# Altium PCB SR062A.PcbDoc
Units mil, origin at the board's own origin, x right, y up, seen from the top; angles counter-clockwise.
Board outline 3000 x 3000 mil, 4 copper layers (Top Layer, Signal Layer 1, Signal Layer 2, Bottom Layer), stack 40.024 mil thick; 38 components, 10 nets, 80 pads, 245 vias.
Unrouted connection lines stored in the file: 3.
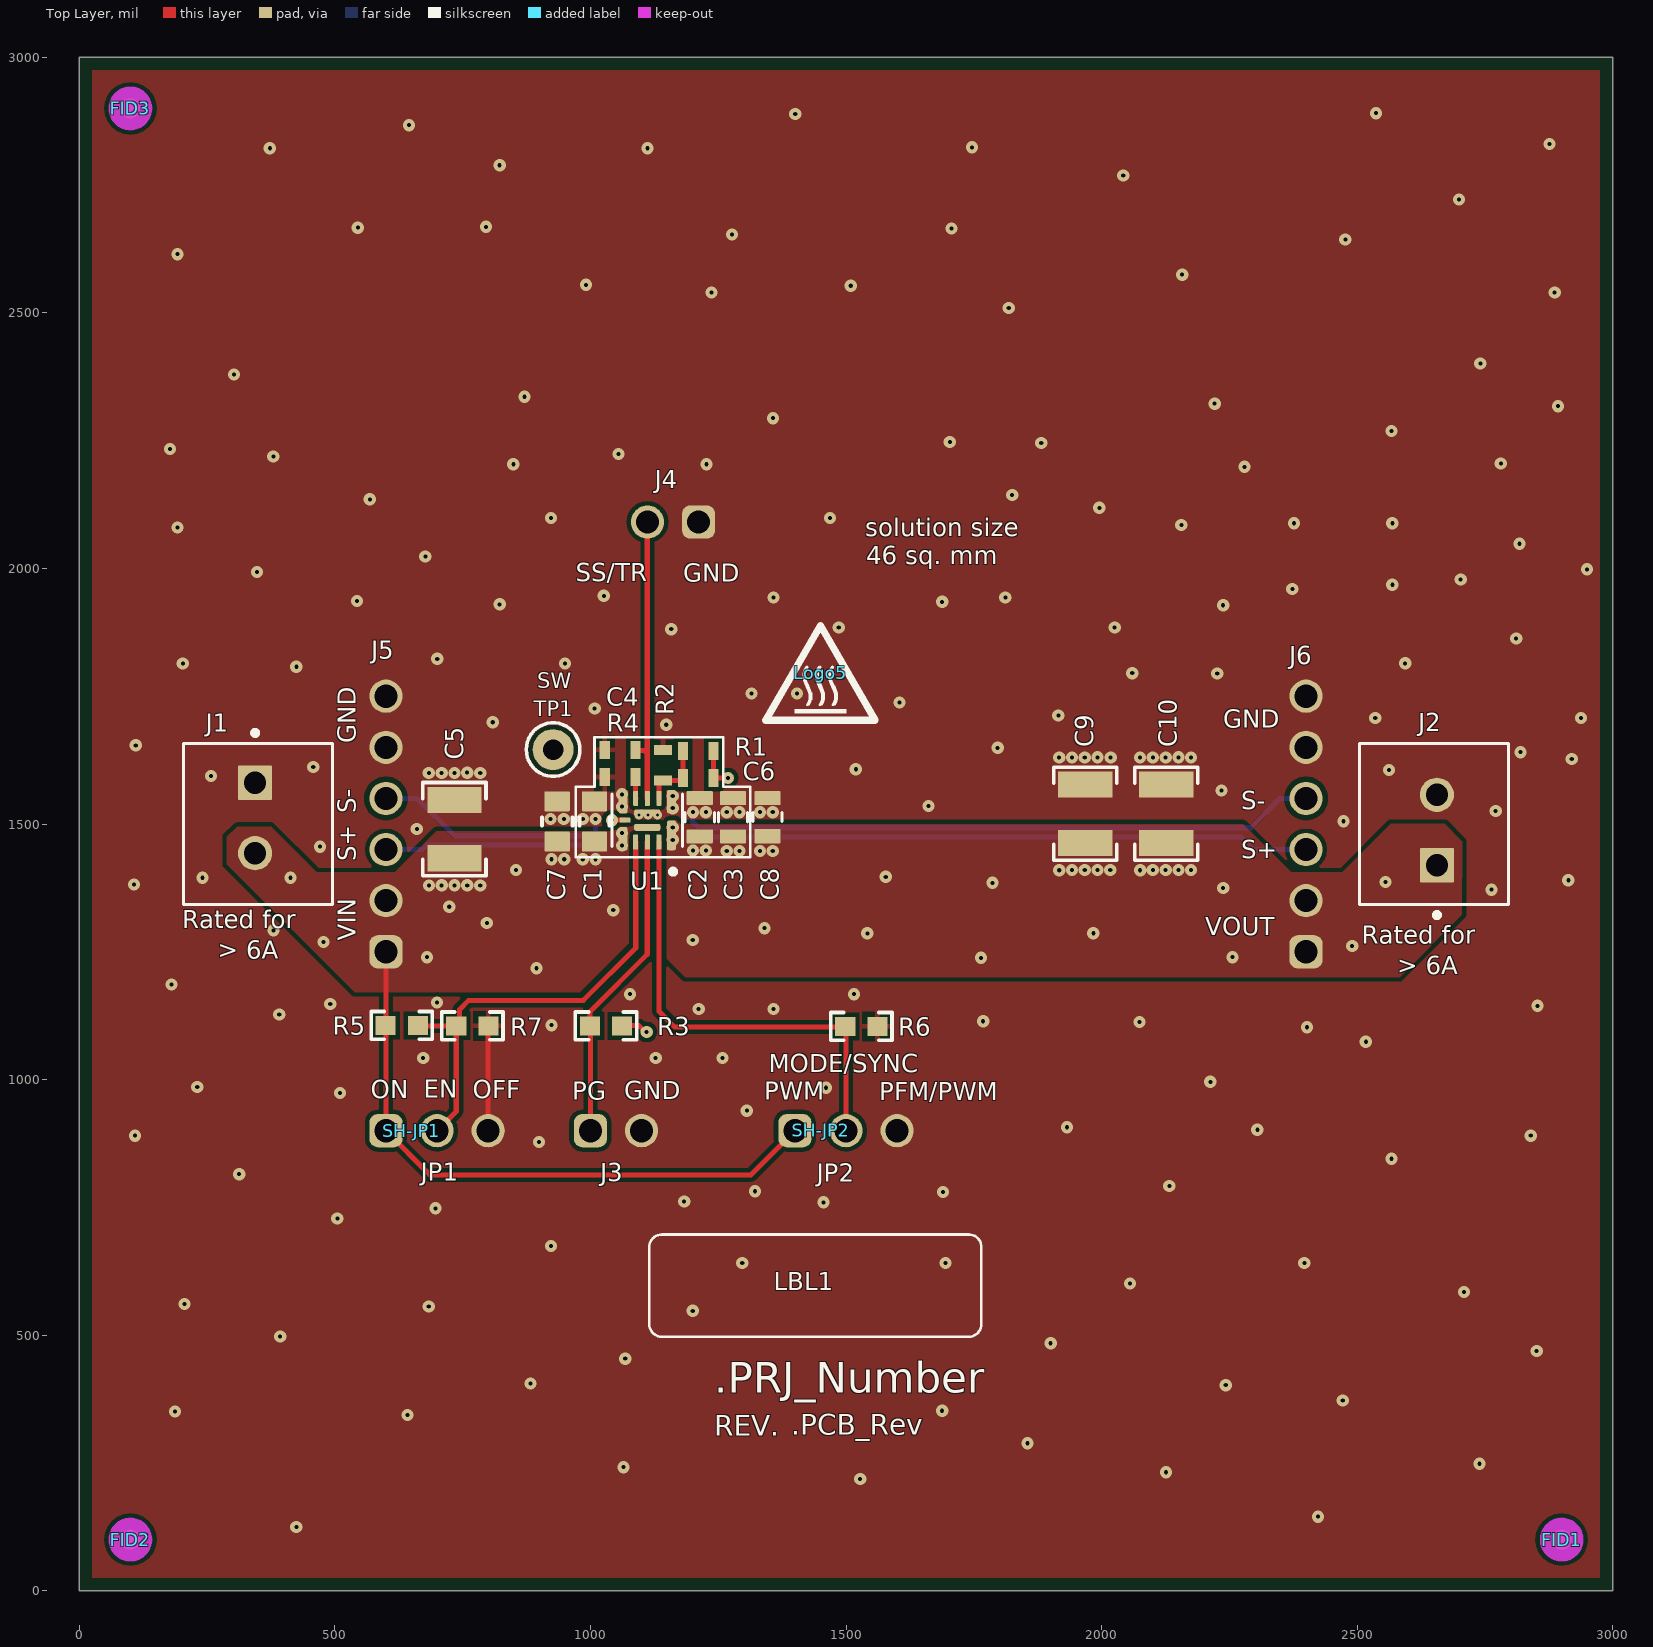
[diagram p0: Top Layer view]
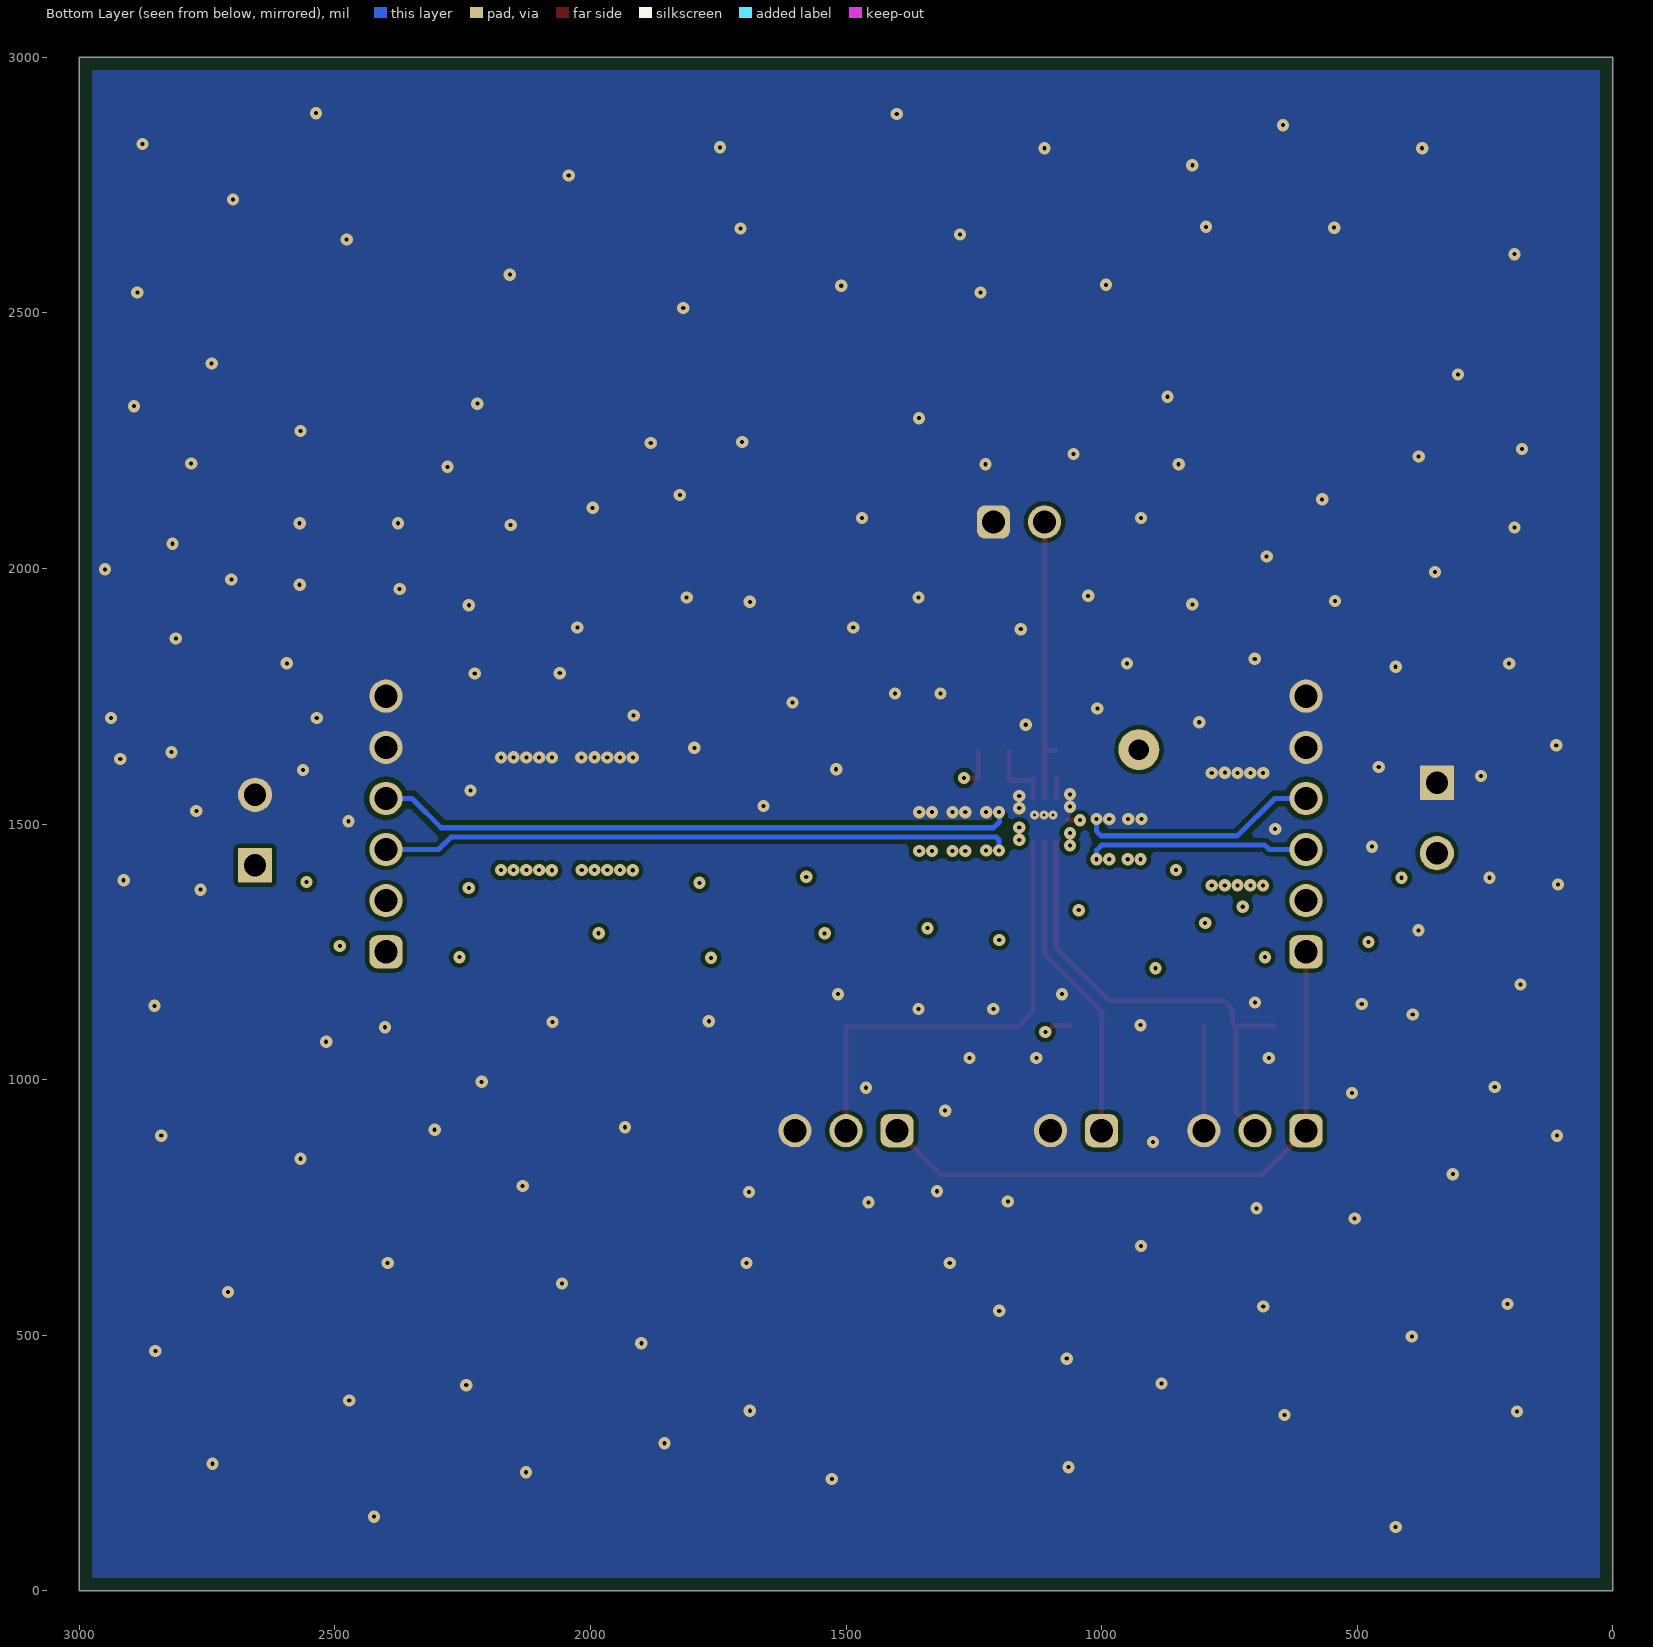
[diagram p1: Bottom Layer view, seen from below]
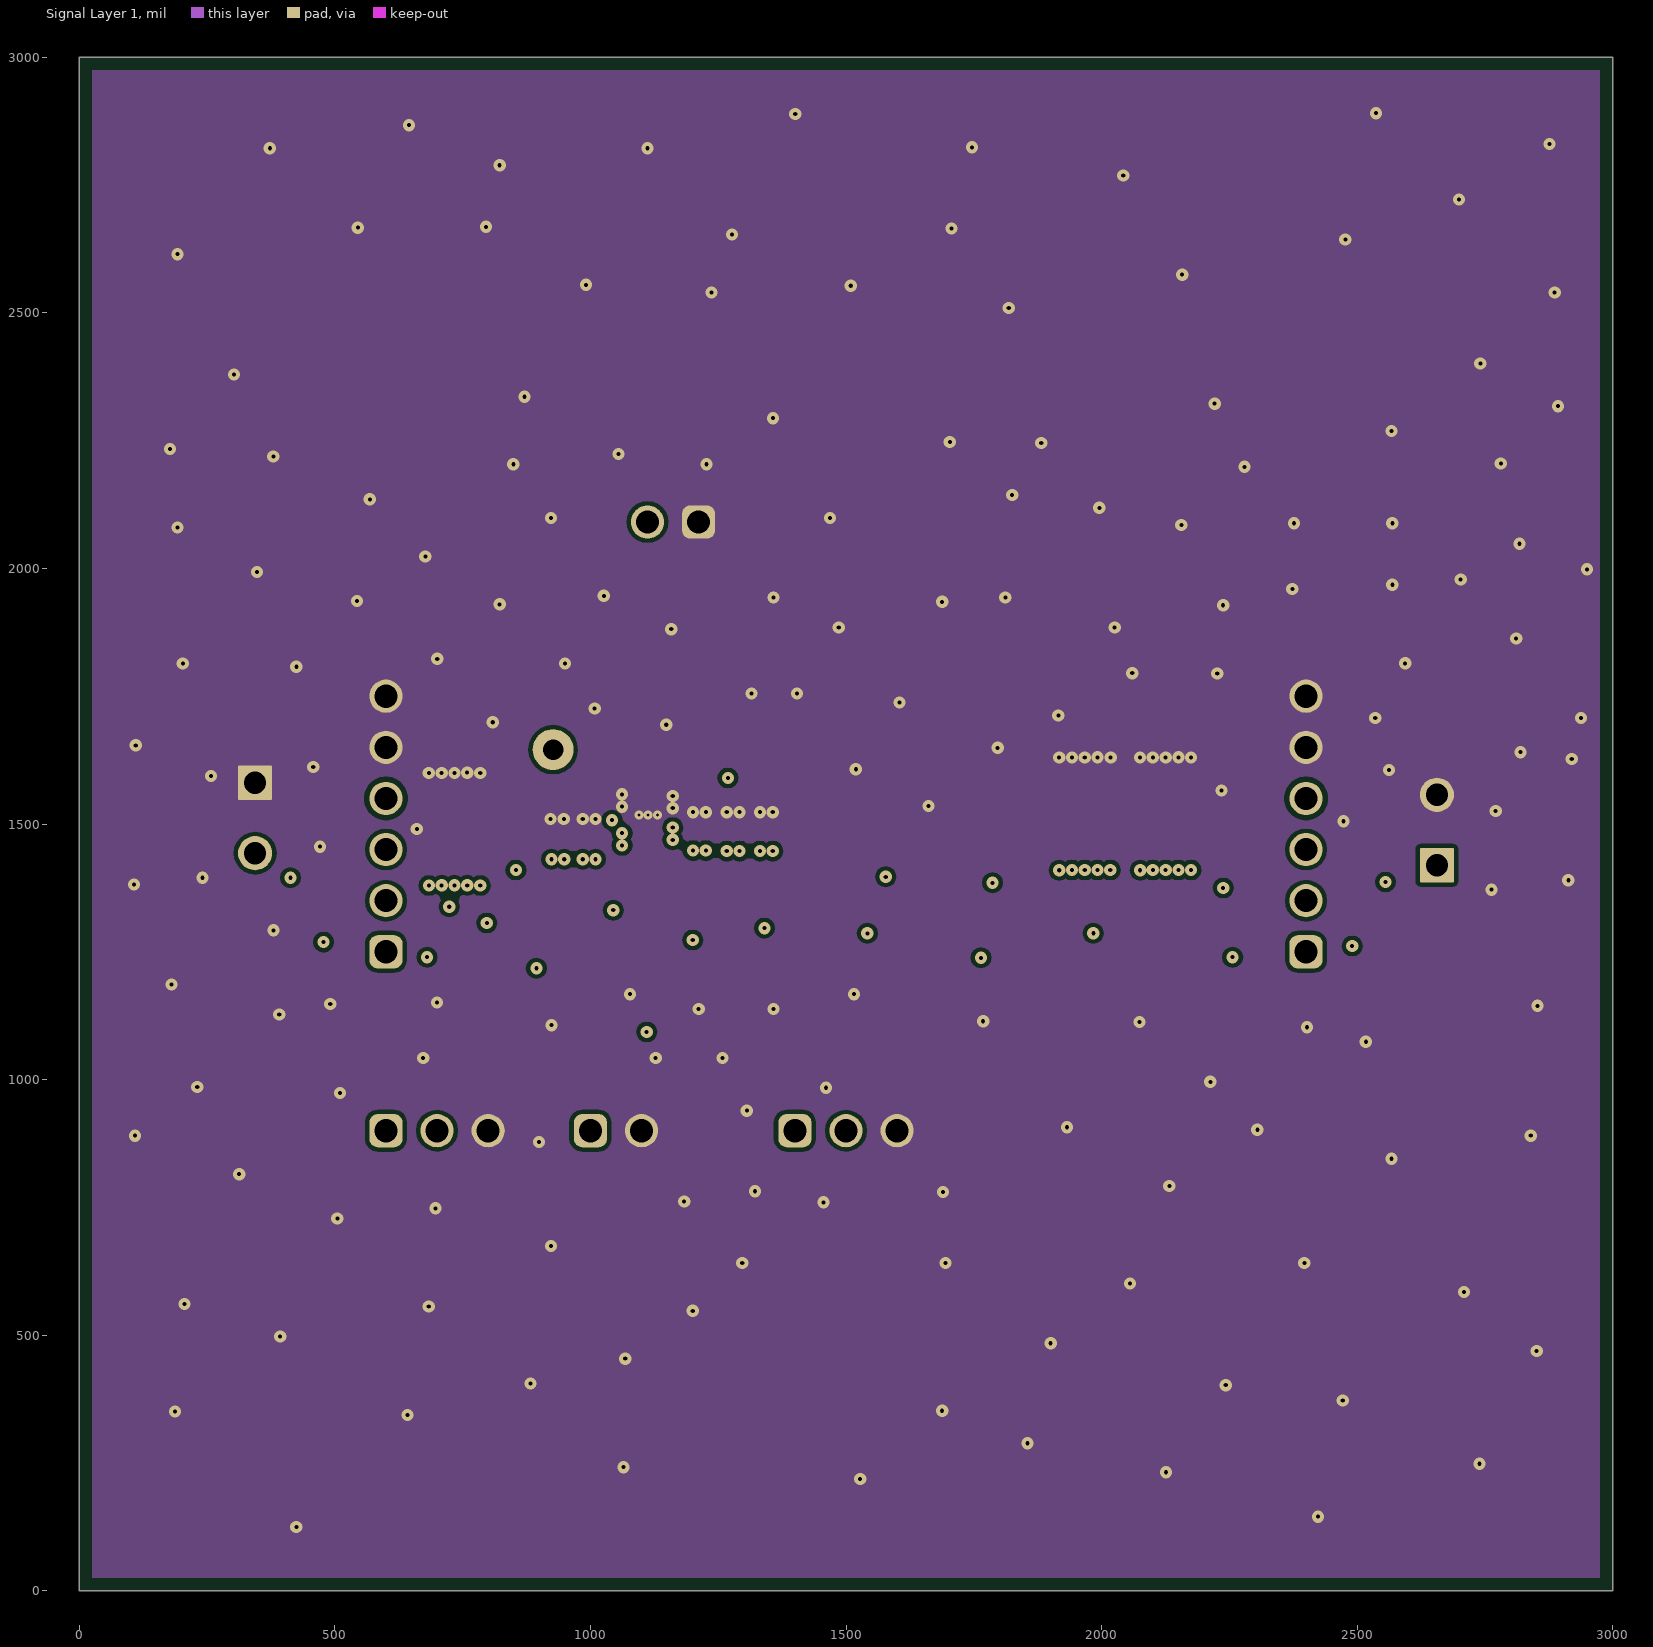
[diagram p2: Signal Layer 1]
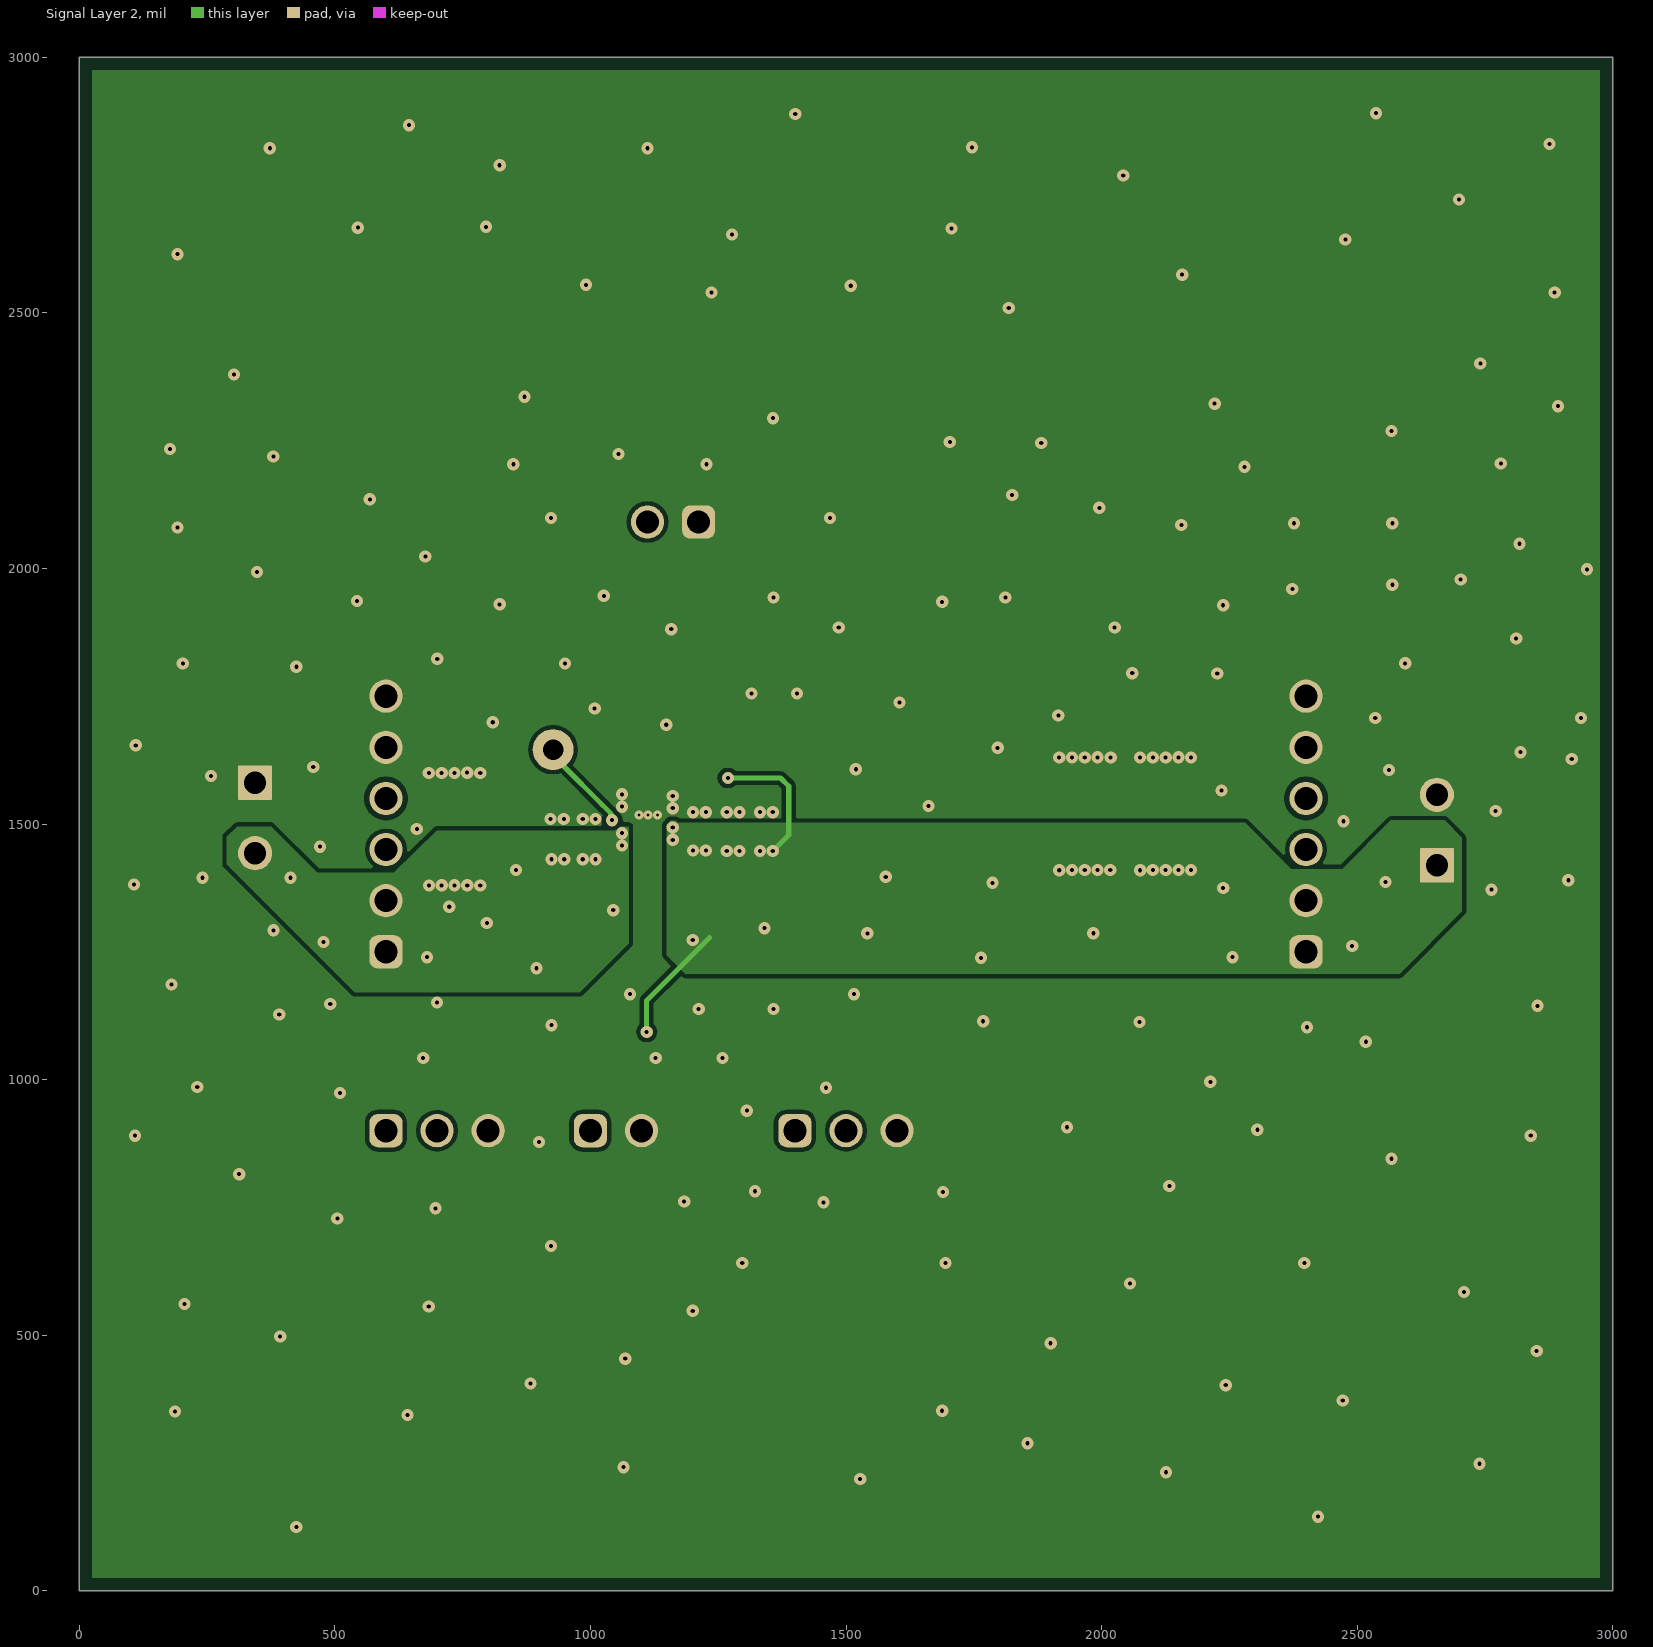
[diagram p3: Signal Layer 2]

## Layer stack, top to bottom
Top Solder: solder mask 0.4, Solder Resist, Dk 3.5
Top Layer: signal copper 2.7559
Dielectric 1: prepreg 5, FR-4 High Tg, Dk 4.2
Signal Layer 1: signal copper 2.7559
Dielectric 2: core 19, FR-4 High Tg, Dk 4.2
Signal Layer 2: signal copper 2.7559
Dielectric 3: prepreg 5, FR-4 High Tg, Dk 4.2
Bottom Layer: signal copper 2.7559
Bottom Solder: solder mask 0.4, Solder Resist, Dk 3.5

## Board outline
0,0 3000,0 3000,3000 0,3000

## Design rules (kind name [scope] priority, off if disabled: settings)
AcuteAngle [All] p1: minimum=4.50000000000000E+0001 checktracksonly=TRUE
AssemblyTestPointUsage [All] p1: valid=2
BoardOutlineClearance BoardOutlineClearance_MountingHoles [OnCopper and InComponentClass('Mounting Holes')] p1: gap=40 ignorepadtopadclearanceinfootprint=FALSE
BoardOutlineClearance BoardOutlineClearance_Poly [OnCopper and IsPoly] p2: gap=25 ignorepadtopadclearanceinfootprint=FALSE
BoardOutlineClearance [OnCopper and Not InComponentClass('Logo') and not InComponentClass('FiducialMark') and not InRegion(1000,500,4000,800) and not InPoly] p3: gap=30 ignorepadtopadclearanceinfootprint=FALSE
Clearance Clearance_U1_Room [WithinRoom('U1_Room')] p1: gap=8 ignorepadtopadclearanceinfootprint=TRUE
Clearance Clearance_Keepouts [((IsTrack Or IsArc) And Not InPoly) And IsFree and IsKeepOut vs ((IsTrack Or IsArc) And Not InPoly) And IsFree and IsKeepOut] p2: gap=0 ignorepadtopadclearanceinfootprint=TRUE
Clearance Clearance_FiducialMark [IsKeepOut and InComponentClass('FiducialMark') vs IsPad and InComponentClass('FiducialMark')] p3: gap=0 ignorepadtopadclearanceinfootprint=TRUE
Clearance [All] p4: gap=8 ignorepadtopadclearanceinfootprint=TRUE
ComponentClearance ComponentClearance_MountingHoles_FiducialMarks [InComponentClass('Mounting Holes') vs InComponentClass('FiducialMark')] p1: gap=50 collisioncheckmode=3 verticalgap=10 showdistances=FALSE
ComponentClearance ComponentClearance_Shunt [InComponentClass('Header') vs InComponentClass('Shunt')] p2: gap=0 collisioncheckmode=3 verticalgap=0 showdistances=FALSE
ComponentClearance ComponentClearance_NT [InComponent('NT1') Or InComponent('NT2')] p3: gap=0 collisioncheckmode=3 verticalgap=0 showdistances=FALSE
ComponentClearance ComponentClearance_Logo [InComponentClass('Logo')] p4: gap=50 collisioncheckmode=3 verticalgap=10 showdistances=FALSE
ComponentClearance ComponentClearance_ScrewToNut [(HasFootprint('NY PMS 440 0025 PH')) vs (HasFootprint('Keystone_1902C'))] p5: gap=5 collisioncheckmode=3 verticalgap=10 showdistances=FALSE
ComponentClearance ComponentClearance_MountingHoles [InComponentClass('Mounting Holes')] p6: gap=100 collisioncheckmode=3 verticalgap=100000 showdistances=FALSE
ComponentClearance ComponentClearance_SmallPassives [HasFootprint('0201*') or HasFootprint('0402*') or HasFootprint('0508') or HasFootprint('0603*') or HasFootprint('0612') or HasFootprint('0805*') or HasFootprint('0815*') or HasFootprint('0830*') or HasFootprint('1206*') or HasFootprint('1210*') or HasFootprint('1808*') or HasFootprint('1812*') or HasFootprint('1825*') or HasFootprint('2010*') or HasFootprint('2220*') or HasFootprint('2225*') or HasFootprint('2512*') or HasFootprint('2728*') or HasFootprint('3518*') vs HasFootprint('0201*') or HasFootprint('0402*') or HasFootprint('0508') or HasFootprint('0603*') or HasFootprint('0612') or HasFootprint('0805*') or HasFootprint('0815*') or HasFootprint('0830*') or HasFootprint('1206*') or HasFootprint('1210*') or HasFootprint('1808*') or HasFootprint('1812*') or HasFootprint('1825*') or HasFootprint('2010*') or HasFootprint('2220*') or HasFootprint('2225*') or HasFootprint('2512*') or HasFootprint('2728*') or HasFootprint('3518*')] p7: gap=14.96 collisioncheckmode=3 verticalgap=10 showdistances=FALSE
ComponentClearance ComponentClearance_THtoSMT [IsThruComponent vs IsSMTComponent] p8: gap=30 collisioncheckmode=3 verticalgap=30 showdistances=FALSE
ComponentClearance ComponentClearance_THtoTH [IsThruComponent vs IsThruComponent] p9: gap=20 collisioncheckmode=3 verticalgap=30 showdistances=FALSE
ComponentClearance [All] p10: gap=15 collisioncheckmode=3 verticalgap=10 showdistances=FALSE
DiffPairsRouting [All] p1: maxlimit=100 minlimit=10 mostfreqgap=10 toplayer_minwidth=15 toplayer_maxwidth=15 toplayer_prefwidth=15 midlayer1_minwidth=15 midlayer1_maxwidth=15 midlayer1_prefwidth=15 midlayer2_minwidth=15 midlayer2_maxwidth=15 midlayer2_prefwidth=15 bottomlayer_minwidth=15 bottomlayer_maxwidth=15 bottomlayer_prefwidth=15 maxuncoupledlength=1000
FabricationTestPointUsage TestPointUsage [All] p1: valid=2 allowmultiple=FALSE
FabricationTestpoint Testpoint [All] p1: side=3 testpointundercomponent=TRUE minsize=40 maxsize=100 preferedsize=60 minholesize=0 maxholesize=40 preferedholesize=32 testpointgrid=1 allowsidetop=TRUE allowsidebottom=TRUE usegrid=TRUE gridtolerance=0.01
FanoutControl Fanout_LCC [IsLCC] p1: bgadir=Out bgaviamode=Centered fanoutstyle=Auto fanoutdirection=Alternating viagrid=1 // Fanout_LCC (Default Rule)
FanoutControl Fanout_BGA [IsBGA] p2: bgadir=Out bgaviamode=Centered fanoutstyle=Auto fanoutdirection=Alternating viagrid=1 // Fanout_BGA (Default Rule)
FanoutControl Fanout_Default [All] p4: bgadir=Out bgaviamode=Centered fanoutstyle=Auto fanoutdirection=Alternating viagrid=1 // Fanout_Default (Default Rule)
FanoutControl Fanout_Small [(CompPinCount < 5)] p5: bgadir=Out bgaviamode=Centered fanoutstyle=Auto fanoutdirection=OutThenIn viagrid=1 // Fanout_Small (Default Rule)
HoleSize HoleSize_HR_Device [WithinRoom('HR_Device')] p1: absolutevalues=TRUE maxlimit=100 minlimit=3.94 maxpercent=80.000 minpercent=20.000
HoleSize [All] p2: absolutevalues=TRUE maxlimit=251 minlimit=5.91 maxpercent=80.000 minpercent=20.000
HoleToHoleClearance HoleToHoleClearance_U1_001 [HasFootprint ('SIE0014A-C01-MFG')] p1: gap=0 allowstackedmicrovias=TRUE
HoleToHoleClearance HoleToHoleClearance_U1_002 [InComponent('U1')] p2: gap=9.84 allowstackedmicrovias=TRUE
HoleToHoleClearance [All] p3: gap=10 allowstackedmicrovias=TRUE
MinimumAnnularRing MinimumAnnularRing_U1 [WithinRoom('U1_Room')] p1: minimumring=3.94
MinimumAnnularRing MinimumAnnularRing_ThermalPadVias [IsVia and InAnyComponent] p2: minimumring=5.91
MinimumAnnularRing [All] p3: minimumring=8
MinimumSolderMaskSliver MinimumSolderMaskSliver_Logo [InComponentClass('Logo') vs InComponentClass('Logo')] p1: minsoldermaskwidth=0.7
MinimumSolderMaskSliver [All] p2: minsoldermaskwidth=3.94
PlaneConnect [All] p1: planeconnectstyle=Relief reliefexpansion=10 reliefentries=4 reliefconductorwidth=10 reliefairgap=10
PolygonConnect PolygonConnect_Rx_Cx [InComponent('C6') or InComponent('R1') or InComponent('R7') or InComponent('R6') or InComponent('R4') or InComponent('R2') or InComponent('C4')] p1: connectstyle=Relief reliefconductorwidth=10 reliefentries=4 polygonreliefangle="90 Angle" airgapwidth=10
PolygonConnect [All] p2: connectstyle=Direct reliefconductorwidth=10 reliefentries=4 polygonreliefangle="90 Angle" airgapwidth=10
RoomDefinition U1_Room [False] p1: confinementstyle=ConfineIn formatcopy=TRUE lockcomponents=FALSE outline 1023,1594.15 1200.13,1594.15 1200.13,1419.36 1023,1419.36
RoutingVias ThermalPadVias [IsVia and InAnyComponent] p1: holewidth=7.87 width=19.68 viastyle="Through Hole" minholewidth=5.9 minwidth=26 maxholewidth=12.99 maxwidth=23.62
RoutingVias [All] p2: holewidth=8 width=24 viastyle="Through Hole" minholewidth=5.91 minwidth=15.75 maxholewidth=40 maxwidth=65 viatemplateguid#1={42F7E421-618C-42AF-BBF7-0934C90EBFC3} viatemplatename#1=v71h20m0mx0
SilkToBoardRegionClearance [Not ((IsComment or IsDesignator) And (Hide <> 'False')) and not InRegion(1000,500,4000,800)] p1:
SilkToSilkClearance SilkToSilkClearance_Pb-FreeLogo [(HasFootprint('Pb-Free_Overlay_Medium') OR HasFootprint('Pb-Free_Overlay_Small')) vs (HasFootprint('Pb-Free_Overlay_Medium') OR HasFootprint('Pb-Free_Overlay_Small'))] p1: silktosilkclearance=0
SilkToSilkClearance [All] p2: silktosilkclearance=4
SilkToSolderMaskClearance SilkToComponentPadClearance [(IsPad or IsFill or IsRegion) and InAnycomponent] p1: minsilkscreentomaskgap=5 clearancetoexposedcopper=TRUE
SilkToSolderMaskClearance "Silk to Solder Mask Opening" [All] p2: minsilkscreentomaskgap=4 clearancetoexposedcopper=FALSE
SolderMaskExpansion [All] p1: expansion=1.97 istentingtop=FALSE
SupplyNets "Schematic Supply Nets" [InNet('GND')] p1: voltage=0.000
Width [All] p1: maxlimit=100 minlimit=10 preferedwidth=10
14 further rules are at their usual default settings.

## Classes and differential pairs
component class Shunt: SH-JP1 SH-JP2
component class Label: LBL1
component class FiducialMark: FID1 FID2 FID3
component class SR062A_Hardware: !PCB FID1 FID2 FID3 LBL1 Logo5 SH-JP1 SH-JP2 ZZ1 ZZ2 ZZ3 ZZ4
component class AssemblyNote: ZZ1 ZZ2 ZZ3 ZZ4
component class SR062A: C1 C2 C3 C4 C5 C6 C7 C8 C9 C10 J1 J2 J3 J4 J5 J6 JP1 JP2 R1 R2 R3 R4 R5 R6 R7 TP1 U1
component class Header: J3 J4 J5 J6 JP1 JP2

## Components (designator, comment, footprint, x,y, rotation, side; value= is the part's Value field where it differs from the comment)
C1 "GRM21BZ71A226ME15L" 0805_HV1 1008,1505 r90 top value=22uF
C2 "GRM21BC80J476ME01L" FP-GRM21BC80J476ME01L_0805-MFG 1213.79,1513.18 r270 top value=47µF
C3 "GRM21BC80J476ME01L" FP-GRM21BC80J476ME01L_0805-MFG 1278.79,1513.18 r270 top value=47µF
C4 "885012206087" 0603S 1058,1645 r180 top value=4700pF
C5 "GRM32ER71A476ME15L" 1210_270 734,1490 r90 top value=47uF
C6 "885012006073" 0603S 1211,1590 r180 top value=10pF
C7 "GRM21BZ71A226ME15L" 0805_HV1 935,1505 r90 top value=22uF
C8 "GRM21BC80J476ME01L" FP-GRM21BC80J476ME01L_0805-MFG 1346.44,1513.39 r270 top value=47µF
C9 "GRM32ED71A476ME15L" 1210_270 1968,1520 r90 top
C10 "GRM32ED71A476ME15L" 1210_270 2126.33,1520 r90 top
FID1 "Fiducial" Fiducial10-20 2900,100 r0 top
FID2 "Fiducial" Fiducial10-20 100,100 r0 top
FID3 "Fiducial" Fiducial10-20 100,2900 r0 top
J1 "691214110002S" FP-691214110002S_HDR2-MFG 350,1500 r270 top
J2 "691214110002S" FP-691214110002S_HDR2-MFG 2650,1500 r90 top
J3 "61300211121" WURTH_61300211121 1050,900 r0 top
J4 "61300211121" WURTH_61300211121 1161.7,2090.66 r180 top
J5 "61300611121" WURTH_61300611121 600,1500 r90 top
J6 "61300611121" WURTH_61300611121 2400,1500 r90 top
JP1 "61300311121" WURTH_61300311121 700,900 r0 top
JP2 "61300311121" WURTH_61300311121 1500,900 r0 top
LBL1 "THT-14-423-10" Label_650x200 1440,597 r180 top
Logo5 "CAUTION HOT SURFACE" IEC_HotSurface_Small 1450,1796 r0 top
R1 "RC0603FR-07200KL" 0603S 1211,1643 r0 top value=200k
R2 "RC0603FR-07100KL" 0603S 1142,1615 r270 top value=100k
R3 "RC0603FR-07100KL" 0603 1030.43,1105 r0 top value=100k
R4 "ERJ-3EKF1002V" 0603S 1058,1592 r0 top value=10.0k
R5 "RC0603FR-07100KL" 0603 631,1106 r180 top value=100k
R6 "RC0603FR-07100KL" 0603 1530,1104 r180 top value=100k
R7 "RC0603FR-07100KL" 0603 769,1105 r180 top value=100k
SH-JP1 "60900213421" Wurth_60900213421 650,900 r180 top
SH-JP2 "60900213421" Wurth_60900213421 1450.2,900.49 r180 top
TP1 "5002" Keystone5002 927,1645.53 r90 top
U1 "TPSM82816PVCAR" VCA0013A-MFG 1111.3,1507.47 r180 top
ZZ1 "This Assembly Note is for PCB labels only" AssemblyNoteLabel 0,3400 r0 top
ZZ2 "These assemblies are ESD sensitive, ESD precautions shall be observed." AssemblyNote 0,3300 r0 top
ZZ3 "These assemblies must be clean and free from flux and all contaminants. Use of no clean flux is not acceptable." AssemblyNote 0,3200 r0 top
ZZ4 "These assemblies must comply with workmanship standards IPC-A-610 Class 2, unless otherwise specified." AssemblyNote 0,3100 r0 top

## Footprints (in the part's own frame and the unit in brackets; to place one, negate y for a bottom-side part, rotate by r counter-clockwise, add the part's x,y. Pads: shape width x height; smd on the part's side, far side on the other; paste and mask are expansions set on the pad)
0603 [mm] "0603 from SM-752 data"
  rect 1x0.95 smd: 1(-0.8,0) 2(0.8,0)
  silkscreen extent -1.52,-0.69 1.52,0.69, body extent -0.87,-0.47 0.87,0.47, height 1
0603S [mil]
  rect 20x35 smd: 1(-30,0) 2(30,0)
  body extent -34,-19 34,19, height 39
0805_HV1 [mm] "Custom footprint based on analyzing multiple manufacturer recommendations"
  rrect10% 1x1.25 smd: 1(-1,0) 2(1,0)
  silkscreen extent -0.2,-0.75 0.2,0.75, body extent -1.1,-0.72 1.1,0.73, height 1.45
1210_270 [mm] "1210"
  rect 1.3x2.7 smd: 1(-1.45,0) 2(1.45,0)
  silkscreen extent -2.32,-1.57 2.32,1.57, body extent -1.7,-1.35 1.7,1.35, height 2.7
AssemblyNote [mil] "Assembly Note"
AssemblyNoteLabel [mil] "Assembly Note for PCB Labels"
Fiducial10-20 [mm]
  round 1 smd mask+0.5: 1(0,0)
  Top Layer keep-out circle w1.178: c0,0 r0.5
FP-691214110002S_HDR2-MFG [mm]
  rrect6% 1.7x1.7 hole 1.1 paste-2539.97 mask+0: 1(-2.05,-0.15)
  round 1.7 hole 1.1 paste-2539.97 mask+0: 2(1.45,-0.15)
  silkscreen extent -4.65,-3.7 4,3.7, body extent -4.1,-3.8 4.1,3.8, height 0.25
FP-GRM21BC80J476ME01L_0805-MFG [mm]
  rrect14% 0.7x1.3 smd paste+0 mask+0: 1(-0.95,0) 2(0.95,0)
  silkscreen extent -0.23,-0.72 0.23,0.72, body extent -1.4,-0.82 1.4,0.82, height 0.25
IEC_HotSurface_Small [mil]
  silkscreen extent -107,-93 107,92
Keystone5002 [mil] "For Keystone 500x miniature loop terminals"
  round 80 hole 40: 1(0,0)
  silkscreen extent -52,-52 52,52, body extent -49,-49 49,49, height 182
Label_650x200 [mil] "Thermal Transfer Label"
  round 1 on Mech13: 0(0,0)
  silkscreen extent -325,-100 325,100, body extent -325,-100 325,100, height 1
VCA0013A-MFG [mm]
  rrect44% 0.45x1.48 smd paste-0.05 mask-0.05: 1(-1.2,0.76)
  rrect44% 0.45x1.16 smd paste-0.05 mask-0.05: 2(-1.2,-0.92) 6(1.2,-0.92) 8(1.2,0.92)
  rrect40% 0.25x0.75 smd paste+0 mask+0.05: 3(-0.575,-1.084) 4(0,-1.084) 5(0.575,-1.084) 9(0.575,1.084) 10(0,1.084) 11(-0.575,1.084)
  rrect40% 0.55x0.25 smd paste+0 mask+0.05: 7(1.1,0)
  rrect57% 1.3x0.35 smd paste-0.05 mask-0.05: 12(0,-0.36) 13(0,0.36)
  silkscreen extent -1.75,-1.3 1.75,2.68, body extent -1.65,-1.56 1.65,1.56, height 0.25
Wurth_60900213421 [mil] "Shunt, 2.54mm, Black"
  round 1 on Mech3: 0(0,0)
  body extent -98,-48 98,48, height 338
WURTH_61300211121 [mm] "Header, 2.54mm, 2x1, TH"
  rrect50% 1.65x1.65 hole 1.15: 1(-1.27,0)
  round 1.65 hole 1.15: 2(1.27,0)
  body extent -2.54,-1.27 2.54,1.27, height 8.54
WURTH_61300311121 [mm] "Header, 2.54mm, 3x1, TH"
  rrect50% 1.65x1.65 hole 1.15: 1(-2.54,0)
  round 1.65 hole 1.15: 2(0,0) 3(2.54,0)
  body extent -3.81,-1.27 3.81,1.27, height 8.54
WURTH_61300611121 [mm] "Header, 2.54mm, 6x1, TH"
  rrect50% 1.65x1.65 hole 1.15: 1(-6.35,0)
  round 1.65 hole 1.15: 2(-3.81,0) 3(-1.27,0) 4(1.27,0) 5(3.81,0) 6(6.35,0)
  body extent -7.62,-1.27 7.62,1.27, height 8.54

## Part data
C1 C7: library part CMP-0008377-2, "CAP, CERM, 22 uF, 10 V, +/- 20%, X7R, 0805", Cap_Case=0805, Manufacturer=MuRata, Supplier Part Number 1=81-GRM21BZ71A226ME5L, TempCo=X7R, Tolerance_%=20%, Value1=Unknown, Value2=10V, ValueDisplayed=22uF
C2 C3 C8: library part CMP-0097404-2, "Chip Multilayer Ceramic Capacitors for General Purpose, 47μF ±20%, X6S(EIA), ±22.0%, 6.3Vdc, 0805 (2012M)", Manufacturer=Murata, Operating Temperature Range="-55°C to +105°C", TempCo=22%, Temperature Characteristic=X6S, Tolerance_%=20%, ValueDisplayed=47uF
C4: library part CMP-0006835-4, "CAP, CERM, 4700 pF, 50 V, +/- 10%, X7R, 0603", Cap_Case=0603, Manufacturer="Wurth Elektronik", Supplier Part Number 1=710-885012206087, TempCo=X7R, Tolerance_%=10%, Value1=Unknown, Value2=50V, ValueDisplayed=4700pF
C5: library part CMP-0009221-2, "CAP, CERM, 47 uF, 10 V, +/- 20%, X7R, 1210", Cap_Case=1210, Manufacturer=MuRata, Supplier Part Number 1=490-6543-1-ND, TempCo=X7R, Tolerance_%=20%, Value1=Unknown, Value2=10V, ValueDisplayed=47uF
C6: library part CMP-0078152-1, "CAP, CERM, 10 pF, 100 V,+/- 5%, C0G/NP0, 0603", Cap_Case=0603, Manufacturer="Wurth Elektronik", TempCo=C0G/NP0, Tolerance_%=5%, Value2=100V, ValueDisplayed=10pF
C9 C10: library part CMP-0086480-2, "47µF ±20% 10V Ceramic Capacitor X7T 1210 (3225 Metric)", Manufacturer=Murata, TempCo=+22-33%, Tolerance_%=20%, ValueDisplayed=47uF
FID1 FID2 FID3: library part CMP-0077181-1, "Fiducial mark.  There is nothing to buy or mount.", Manufacturer=N/A
J1 J2: library part CMP-0093089-2, "2 Position Wire to Board Terminal Block Horizontal with Board 0.138\" (3.50mm) Through Hole", Current_A=10A, Digikey Part Number=732-691214110002S-ND, Manufacturer=Wurth, Mouser Part Number=710-691214110002S, Operating Temperature Range="-30°C to +120°C", Voltage_V=300V
J3 J4: library part CMP-0054794-2, "Header, 2.54 mm, 2x1, Gold, TH", Color=Black, Manufacturer="Wurth Elektronik", Supplier Part Number 1=732-5315-ND
J5 J6: library part CMP-0054801-2, "Header, 2.54 mm, 6x1, Gold, TH", Color=Black, Manufacturer="Wurth Elektronik", Supplier Part Number 1=732-5319-ND
JP1 JP2: library part CMP-0054796-4, "Header, 2.54 mm, 3x1, Gold, TH", Manufacturer="Wurth Elektronik", Supplier Part Number 1=732-5316-ND
LBL1: library part CMP-0003625-1, "Thermal Transfer Printable Labels, 0.650\" W x 0.200\" H - 10,000 per roll", Manufacturer=Brady, Supplier Part Number 1=97C5133
Logo5: library part CMP-0074837-2, "IEC 61010-1 Hot Surface Warning", Manufacturer="Texas Instruments"
R1: library part CMP-0022901-4, "RES, 200 k, 1%, 0.1 W, 0603", Manufacturer=Yageo, Power_W=100mW, Supplier Part Number 1=311-200KHRCT-ND, TempCo="100 ppm/C", Tolerance_%=1%, Value2=0.1W, Value_Code=200k
R2 R3 R5 R6 R7: library part CMP-0022735-5, "RES, 100 k, 1%, 0.1 W, 0603", Manufacturer=Yageo, Power_W=100mW, Supplier Part Number 1=311-100KHRCT-ND, TempCo="100 ppm/C", Tolerance_%=1%, Value2=0.1W, Value_Code=100k
R4: library part CMP-0022684-3, "RES, 10.0 k, 1%, 0.1 W, 0603", Manufacturer=Panasonic, Power_W=100mW, Supplier Part Number 1=P10.0KHCT-ND, TempCo="100 ppm/C", Tolerance_%=1%, Value2=0.1W, Value_Code=10k0, ValueDisplayed=10.0k
SH-JP1 SH-JP2: library part CMP-0003761-2, "Shunt, 2.54mm, Gold, Black", Manufacturer="Wurth Elektronik", Supplier Part Number 1=732-2678-ND
TP1: library part CMP-0055139-2, "Test Point, Miniature, White, TH", Color=White, Manufacturer="Keystone Electronics", Supplier Part Number 1=36-5002-ND
U1: library part CMP-0120848-2, "2.7-V to 6-V Input 6-A Step-Down Power Module with Integrated Inductor and Frequency Synchronization", Manufacturer="Texas Instruments", Max Supply Voltage=6V, Min Supply Voltage=2.7V, Nominal Supply Current=18uA, Operating Temperature Range="-40°C to +125°C", Output Voltage=0.6-5.5V, Switching Frequency=1.8-4MHz
ZZ1: library part CMP-0003616-3
ZZ2: library part CMP-0077236-1
ZZ3: library part CMP-0077237-1
ZZ4: library part CMP-0077238-1

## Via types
v1: diameter 24, hole 8, Top Layer to Bottom Layer, tented both sides, 242 vias
v2: diameter 17.72, hole 5.91, Top Layer to Bottom Layer, tented both sides, 3 vias

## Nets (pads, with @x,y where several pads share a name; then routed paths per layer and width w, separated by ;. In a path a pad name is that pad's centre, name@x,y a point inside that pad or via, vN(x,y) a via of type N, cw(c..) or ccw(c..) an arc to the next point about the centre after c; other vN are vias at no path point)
GND: C1.2 C2.1 C3.1 C4.2 C5.2 C7.2 C8.1 C9.2 C10.2 J1.1 J2.2 J3.2 J4.1 J5.4 J5.5 J5.6 J6.4 J6.5 J6.6 JP1.3 JP2.3 R2.1 R4.1 R6.1 R7.1 U1.2 U1.6 U1.12 | length 1921.8
  Top Layer w10: R7.1@799,1106 800,1105 JP1.3
  Bottom Layer w10: J5.4 661,1550 734,1477 1001,1477 1010,1486 v1(1010,1510) ; v1@1199.96,1523 1199.96,1504.04 1211.31,1492.69 2291.69,1492.69 2348.97,1550 J6.4
  other v1: 424.75,124.88 2423.37,144.94 1527.67,218.46 2125.92,231.83 1064.78,241.86 2739.21,248.54 1855.2,288.65 641.99,343.8 187.45,350.48 1688.09,352.15 2471.83,372.2 2242.89,402.28 882.63,405.63 1068.12,454.09 2851.17,469.13 1900.32,484.17 393,497.54 1200.13,547.67 683.77,556.02 205.83,561.04 2709.13,584.43 2055.73,601.14 1297.06,641.25 1694.78,641.25 2396.63,641.25 922.73,674.67 504.96,728.15 697.14,748.2 1455.81,759.9 1183.42,761.57 1689.76,779.95 1322.12,781.62 2132.6,791.65 312.78,815.04 2567.08,845.12 899.25,878.03 108.91,890.24 2839.47,890.24 2304.72,901.94 1932.48,906.72 1305.96,939.16 509.97,973.8 1461,984 230.9,985.49 2212.81,995.52 672.81,1042.31 1127.71,1042.31 1258.62,1042.31 2516.95,1074.06 2401.65,1102.47 923.81,1106.5 2074.11,1112.5 1768.3,1114.17 391.33,1127.54 1211.7,1138.32 1358.2,1138.32 2852.84,1144.25 491,1148 700,1151 1077.36,1167.1 1515.78,1167.1 180.65,1186.12 380,1292 2762.6,1371.52 107.24,1381.54 2913,1389.9 240.93,1394.91 470.79,1455.59 660.41,1490.08 2473.25,1505.33 922.1,1509.79 948,1510 985,1510 1200.76,1523.18 1225.76,1523.18 1266.75,1523.18 1291.75,1523.18 1331.75,1523.18 1356.75,1523.18 2770.96,1525.26 1161,1531 1062,1534 1661.35,1535.28 1161,1555 1062,1558 2234.54,1565.36 257.64,1593.77 684,1599.91 709,1599.91 734,1599.91 758.9,1600.37 784.5,1599.91 2562.07,1605.47 1519.31,1607.14 457.83,1611.68 2919.69,1627.19 1917,1629.91 1942,1629.91 1967,1629.91 1991.9,1630.37 2017.72,1629.91 2075.33,1629.91 2100.33,1629.91 2125.33,1629.91 2150.23,1630.37 2175,1629.91 2819.42,1640.56 1796.71,1648.92 110.58,1653.93 1148.31,1694.14 809,1699 2535.33,1707.41 2938.07,1707.41 1915.36,1712.42 1008.31,1726.14 1604.54,1737.49 1315.04,1755.52 1403.96,1755.52 2226.18,1794.3 2060,1795 424.75,1807.67 202.65,1814.12 950.5,1814.12 2593.82,1814.36 700.31,1823.14 2811.06,1862.82 1158.09,1881.12 1485.89,1884.54 2025.65,1884.54 2237.88,1927.99 822.47,1929.66 1688.09,1934.67 543.39,1936.34 1358.2,1943.03 1811.75,1943.03 1026.34,1946.37 2373.24,1959.74 2568.76,1968.1 2702.44,1978.12 347.88,1993.16 2949.76,1998.18 677.08,2023.24 2817.75,2048.31 192.47,2080.06 2156,2085.07 2376.58,2088.41 2568.76,2088.41 922.73,2098.44 1468.82,2098.44 1995.57,2118.49 568.45,2135.12 1825.12,2143.56 2279.66,2198.71 849.2,2203.72 1227.2,2203.72 2780.98,2205.39 379.65,2219.12 1054.75,2223.77 177.43,2233.8 1881.94,2245.5 1703.13,2247.17 2567.08,2268.89 1357.22,2293.96 2892.95,2317.35 2221.17,2322.37 870.93,2335.74 302.76,2379.18 2740.88,2400.91 1818.44,2509.53 1236.9,2539.61 2886.26,2539.61 1509.29,2552.98 991.25,2554.65 2157.67,2574.7 192.47,2614.81 2476.85,2643.22 1277,2653.24 1706.47,2664.94 545.07,2666.61 795.73,2668.28 2699.1,2721.76 2042.36,2768.55 822.47,2788.6 372.94,2822.02 1111.57,2822.02 1746.58,2823.69 2876.24,2830.38 645.33,2867.14 1400.66,2888.87 2537.01,2890.54
  other v2: 1095,1518 1113,1518 1131,1518
NetC4_1: C4.1 J4.2 U1.4 | length 570.2
  Top Layer w10: C4.1@1089,1644 1105.45,1644 1111.3,1638.14 ; U1.4 1111.3,1638.14 ; J4.2 1111.3,2090.27 1111.3,1638.14
  Bottom Layer w10: J4.2@1107.72,2085.07 J4.2@1111.08,2081.71
NetC6_2: C6.2 R1.1 R2.2 U1.3 | length 138.5
  Top Layer w10: R2.2@1132.16,1585.98 R2.2@1135.3,1589.13 ; U1.3 1133.94,1580 1138.94,1585 R2.2 1176,1585 C6.2 R1.1
NetJP1_2: JP1.2 R5.1 R7.2 U1.9 | length 935.4
  Top Layer w10: R5.1 663.5,1105 R7.2 ; JP1.2 737.5,937.5 R7.2 ; U1.9 1088.67,1257.67 986,1155 762.04,1155 744.28,1137.25 744.28,1111.78 R7.2
  Bottom Layer w10: JP1.2@700,897 JP1.2
NetJP2_2: JP2.2 R6.2 U1.11 | length 913.8
  Top Layer w10: U1.11 1133.94,1133.79 1165.22,1102.5 1497.01,1102.5 R6.2 1500,1102.5 JP2.2
NetR4_2: R4.2 U1.5 | length 42.1
  Top Layer w10: R4.2 1088.59,1591.41 1088.59,1550.23 U1.5
NetTP1_1: TP1.1 U1.7 | length 173.8
  Top Layer w10: v1(1042.41,1507.47) U1.7
  Signal Layer 2 w10: TP1.1@945.21,1615.43 1023,1537.64 1039.73,1520.92 1039.73,1510.15 v1(1042.41,1507.47)
PG: J3.1 R3.1 U1.10 | length 611
  Top Layer w10: R3.1 999.11,1105.18 999.11,1132.84 1111.3,1245.04 U1.10 ; J3.1 1000,1102.5 R3.1@1001.5,1104
VIN: C1.1 C5.1 C7.1 J1.2 J5.1 J5.2 J5.3 JP1.1 JP2.1 R5.2 U1.8 U1.13 | length 1657.7
  Top Layer w10: R5.2 600,1106.5 J5.1 ; R5.2@601,1106 600,1105 JP1.1 686.4,813.6 1313.6,813.6 JP2.1
  Bottom Layer w10: J5.3 671.63,1450 680.63,1459 999.39,1459 1009.6,1448.78 1009.6,1431.4 v1(1010,1431)
  other v1: 894.32,1217.78 680.42,1239.5 478,1269 797.4,1306.34 1044.72,1331.41 723.87,1338.09 684.1,1379.54 709,1380 734,1380 759,1380 784.5,1379.54 413.28,1394.91 854.22,1409.95 923.81,1431.07 948.81,1431.07 985,1431 1062,1458 1062,1482
VOUT: C2.2 C3.2 C6.1 C8.2 C9.1 C10.1 J2.1 J6.1 J6.2 J6.3 R1.2 R3.2 U1.1 | length 1874.2
  Top Layer w10: R3.2 1063.02,1106.09 1094.61,1106.09 1107.57,1093.13 v1(1110,1093.13) ; R1.2 C6.1 v1(1269,1590)
  Signal Layer 2 w10: v1(1110,1093.13) 1110,1154.72 1232.96,1277.68 ; v1(1269,1590) 1372,1590 1388,1574 1388,1478.23 v1(1356.75,1446.98) v1@1355,1447
  Bottom Layer w10: v1@1203.43,1450.66 v1(1200.76,1447.98) 1200.76,1468.8 1206.61,1474.66 1221.59,1474.66 2272.31,1474.69 2297,1450 J6.3
  other v1: 1763.96,1238.26 2256.26,1239.5 2490.21,1261.22 1200.13,1273 1541.81,1286.08 1983.87,1286.29 1340.5,1296.32 2237.88,1374.86 1786.69,1384.89 2555.39,1386.56 1577.8,1396.58 1917.1,1409.54 1942,1410 1967,1410 1992,1410 2017,1409.91 2075.42,1409.54 2100.33,1410 2125.33,1410 2150.33,1410 2175,1410 1266.75,1446.98 1291.75,1446.98 1331.75,1446.98 1225.76,1447.98 1161,1469 1161,1493
pads on no net: FID1.1 FID2.1 FID3.1 LBL1.0 SH-JP1.0 SH-JP2.0

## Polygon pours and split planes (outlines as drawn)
VOUT on Top Layer "TOP_LAYER_VOUT_P194" (solid, remove dead copper, pour order 194): 1176.28,1499.87 2276.76,1499.74 2371.37,1405.13 2470.75,1405.13 2565.94,1500.32 2671.47,1500.32 2705,1466.68 2705.06,1466.73 2705.02,1322.28 2582.87,1200.13 1185.34,1200.13 1149.03,1236.45 1148.98,1501.42 1149.03,1507.76 1168,1507.76
VIN on Top Layer "TOP_LAYER_VIN_P193" (solid, remove dead copper, pour order 193): 1046,1486.14 1064,1499.87 1084.64,1499.87 1137,1499.87 1137,1487 1090,1487 1074.58,1471.58 1074.58,1266.58 978.98,1170.98 798.42,1170.99 538.7,1170.99 288.77,1420.92 288.77,1474.84 308.93,1495 375.25,1495 464.73,1405.52 618.48,1406.48 698.14,1486.14
GND on Top Layer "tga" (solid, remove dead copper, pour order 201): 0,3000 3000,3000 3000,0 0,0
VIN on Signal Layer 2 "SIGNAL_LAYER_2_VIN_P198" (solid, remove dead copper, pour order 198): 1075,1495 1057,1495 1048,1487 699,1487 616.44,1405.44 465.76,1404.5 375.25,1495 308.93,1495 288.77,1474.84 288.77,1420.92 538.7,1170.99 798.42,1170.99 978.98,1170.98 1075,1267
VOUT on Signal Layer 2 "SIGNAL_LAYER_2_VOUT_P182" (solid, remove dead copper, pour order 182): 1167,1506 1171.04,1501.96 2281.11,1502.04 2371.39,1411.75 2470.77,1411.75 2565.96,1506.94 2671.49,1506.94 2705.02,1473.3 2705.04,1328.91 2582.89,1206.75 1185.36,1206.75 1149.04,1243.07 1149,1506
GND on Signal Layer 2 "tga" (solid, remove dead copper, pour order 199): 0,3000 3000,3000 3000,0 0,0
GND on Signal Layer 1 "SIGNAL_LAYER_1_GND_P186" (solid, remove dead copper, pour order 186): 0,3000 0,0 3000,0 3000,3000
GND on Bottom Layer "BOTTOM_LAYER_GND_P164" (solid, remove dead copper, pour order 164): 0,3000 3000,3000 3000,0 0,0

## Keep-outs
Keep-Out Layer:
  text ".Layer_Name" at 577,-858.49 h60

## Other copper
Top Layer:
  pour cut-out: 2400,1507.25 cw(c2400,1550) 2357.26,1550 cw(c2400,1550) 2400,1592.74 cw(c2400,1550) 2442.75,1550 cw(c2400,1550)
  pour cut-out: 600,1507.25 cw(c600,1550) 557.26,1550 cw(c600,1550) 600,1592.74 cw(c600,1550) 642.75,1550 cw(c600,1550)
  text ".Layer_Name" at 577,-858.49 h60
Signal Layer 1:
  pour cut-out: 2400,1507.25 cw(c2400,1550) 2357.26,1550 cw(c2400,1550) 2400,1592.74 cw(c2400,1550) 2442.75,1550 cw(c2400,1550)
  pour cut-out: 600,1507.25 cw(c600,1550) 557.26,1550 cw(c600,1550) 600,1592.74 cw(c600,1550) 642.75,1550 cw(c600,1550)
  text ".Layer_Name" at 569.27,-866.18 h60
Signal Layer 2:
  pour cut-out: 2400,1507.25 cw(c2400,1550) 2357.26,1550 cw(c2400,1550) 2400,1592.74 cw(c2400,1550) 2442.75,1550 cw(c2400,1550)
  pour cut-out: 600,1507.25 cw(c600,1550) 557.26,1550 cw(c600,1550) 600,1592.74 cw(c600,1550) 642.75,1550 cw(c600,1550)
  text ".Layer_Name" at 569.27,-866.18 h60
Bottom Layer:
  pour cut-out: 2400,1507.25 cw(c2400,1550) 2357.26,1550 cw(c2400,1550) 2400,1592.74 cw(c2400,1550) 2442.75,1550 cw(c2400,1550)
  pour cut-out: 600,1507.25 cw(c600,1550) 557.26,1550 cw(c600,1550) 600,1592.74 cw(c600,1550) 642.75,1550 cw(c600,1550)
  pour cut-out: 600,1508.38 cw(c600,1550) 558.38,1550 cw(c600,1550) 600,1591.62 cw(c600,1550) 641.62,1550 cw(c600,1550)
  pour cut-out: 1184,1520 1187,1523 1211,1523 1214,1520 1214,1507 2284.34,1507 2342.64,1565.29 2400,1565.29 2400,1530.42 2399.56,1529.98 2351.02,1529.98 2300.33,1479.29 1184,1479.29
  pour cut-out: 666.43,1565.29 741.72,1490 985.86,1490 1005.86,1510 1023.17,1510 1023.17,1475.39 1015.78,1468 720.94,1468 654.23,1534.71 604.21,1534.71 604.21,1565.29
  text ".Layer_Name" at 577,-858.49 h60

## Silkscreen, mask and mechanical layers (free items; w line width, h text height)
Top Overlay:
  lines w5: 971,1435 1313.11,1435 1312.83,1573 1260,1573 1260,1670 1008.02,1670 1008.02,1573 971,1573 971,1435
  text "solution size" at 1537.67,2062.83 h35
  text "46 sq. mm" at 1539.67,2008.5 h35
  text "SS/TR" at 971,1975 h35
  text "GND" at 1182,1974 h35
  text "SW" at 896,1766 h30
  text "GND" at 2238.04,1687.99 h35
  text "GND" at 540.75,1658.24 h35 r90
  text "S-" at 2273.03,1528.99 h35
  text "S-" at 540.75,1521.26 h35 r90
  text "S+" at 2273.03,1432.99 h35
  text "S+" at 540.75,1427.51 h35 r90
  text "Rated for" at 201.95,1296 h35
  text "VOUT" at 2203.05,1281.99 h35
  text "VIN" at 540.75,1271.24 h35 r90
  text "Rated for" at 2509.18,1265.87 h35
  text "> 6A" at 270.71,1236 h35
  text "> 6A" at 2577.94,1205.87 h35
  text "MODE/SYNC" at 1349,1014 h35
  text "EN" at 673.98,964.64 h35
  text "ON" at 570.55,963.81 h35
  text "OFF" at 769.9,963.81 h35
  text "GND" at 1066.41,962 h35
  text "PG" at 964,961 h35
  text "PWM" at 1340.5,961 h35
  text "PFM/PWM" at 1565,960 h35
  text ".PRJ_Number" at 1242.33,387.8 h60
  text ".PCB_Rev" at 1393,305 h40
  text "REV." at 1242,303 h40
  text ".Layer_Name" at 577,-858.49 h60
Bottom Overlay:
  text ".Layer_Name" at 577,-858.49 h60
Top Paste:
  text ".Layer_Name" at 577,-858.49 h60
Bottom Paste:
  text ".Layer_Name" at 577,-858.49 h60
Top Solder:
  text ".Layer_Name" at 577,-858.49 h60
  text ".Layer_Name" at 577,-858.49 h60
Bottom Solder:
  text ".Layer_Name" at 577,-858.49 h60
Drill Guide:
  text ".Layer_Name" at 577,-858.49 h60
M1 Board Outline:
  the board outline again, w10
  text ".Layer_Name" at 577,-858.49 h60
M2 Board Dimensions:
  rectangle: 0,-275 125,-150
  rectangle: 125,-400 500,-275
  lines w7: 0,-275 1000,-275 ; 125,-400 125,-150 ; 250,-400 250,-150 ; 500,-400 500,-150 ; 750,-400 750,-150 ; 0,-400 1000,-400 1000,-150 0,-150 0,-400
  text ".Layer_Name" at 577,-858.49 h60
M3 3D STEP Top:
  text ".Layer_Name" at 577,-858.49 h60
M4 3D STEP Bottom:
  text ".Layer_Name" at 577,-858.49 h60
Top M5 Assembly Top/M6 Assembly Bottom:
  lines w10: -292,-930.17 6308,-930.17 ; -292,-726.83 6310,-726.83 ; -292,-523.5 -292,-1133.5 3713,-1133.5 6310,-1133.5 6310,-523.5 -291.5,-523.5 -291.5,-1133.5 1284,-1133.5 ; 2173,-1133.5 2173,-523.5 ; 3440,-726.83 3440,-523.5 ; 4280,-726.83 4280,-523.5 ; 4902,-1140 4902,-937.17
  text "COMPONENTS MARKED 'DNP' SHOULD NOT BE POPULATED." at 1153.5,-318.5 h60
  text "ASSEMBLY VARIANT:" at 1153,-434 h60
  text ".VariantName" at 2189,-434 h60
  text "PCB VIEWED FROM TOP SIDE" at -228.5,-655.67 h60
  text "BOARD #:" at 2248,-655.67 h60
  text ".PRJ_Number" at 2793.5,-655.67 h60
  text "REV:" at 3638,-655.67 h60
  text ".PCB_Rev" at 3929.5,-655.67 h60
  text "SVN REV:" at 4476,-655.67 h60
  text ".VersionControl_RevNumber" at 4982,-655.67 h60
  text "TID #:" at 2248,-859 h60
  text ".TID" at 2793.5,-859 h60
  text "PLOT NAME =" at -228.5,-1064.34 h60
  text ".plot_File_Name" at 577,-1064.34 h60
  text "GENERATED    :" at 2250,-1064.34 h60
  text ".Print_Date" at 3119.5,-1064.34 h60
  text ".Print_Time" at 3848.5,-1064.34 h60
  text "TEXAS INSTRUMENTS" at 5113,-1064.34 h60
Bottom M5 Assembly Top/M6 Assembly Bottom:
  lines w10: -292.5,-727.33 6309.5,-727.33 ; -290.5,-930.67 6309.5,-930.67 ; 1115.5,-1140.5 1115.5,-937.67 ; 1737.5,-727.33 1737.5,-524 ; 2577.5,-727.33 2577.5,-524 ; 3844.5,-1134 3844.5,-524 ; 4733.5,-1134 6309,-1134 6309,-524 -292.5,-524 -292.5,-1134 2304.5,-1134 6309.5,-1134 6309.5,-524
  text "COMPONENTS MARKED 'DNP' SHOULD NOT BE POPULATED." at 6102,-318 h60
  text ".VariantName" at 5058,-434 h60
  text "ASSEMBLY VARIANT:" at 6097,-434 h60
  text ".VersionControl_RevNumber" at 1035.5,-656.17 h60
  text "SVN REV:" at 1541.5,-656.17 h60
  text ".PCB_Rev" at 2088,-656.17 h60
  text "REV:" at 2379.5,-656.17 h60
  text ".PRJ_Number" at 3224,-656.17 h60
  text "BOARD #:" at 3769.5,-656.17 h60
  text "PCB VIEWED FROM BOTTOM SIDE" at 6246,-656.17 h60
  text ".TID" at 3224,-859.5 h60
  text "TID #:" at 3769.5,-859.5 h60
  text "TEXAS INSTRUMENTS" at 904.5,-1064.84 h60
  text ".Print_Time" at 2169,-1064.84 h60
  text ".Print_Date" at 2898,-1064.84 h60
  text "GENERATED    :" at 3767.5,-1064.84 h60
  text ".plot_File_Name" at 5440.5,-1064.84 h60
  text "PLOT NAME =" at 6246,-1064.84 h60
M9 Title Sheet:
  drawing of 57 lines, arcs and shapes, not listed
  text "1" at 739.84,8036.5 h70
  text "2" at 3235.5,8036.5 h70
  text "3" at 5724.84,8036.5 h70
  text "4" at 8231.51,8036.5 h70
  text "5" at 10730.5,8036.5 h70
  text "6" at 13235.5,8036.5 h70
  text "A" at -416.5,6893.5 h70
  text "A" at 14383.5,6893.5 h70
  text "B" at -416.5,4513.5 h70
  text "B" at 14383.5,4513.5 h70
  text "C" at -416.5,2138.5 h70
  text "C" at 14383.5,2138.5 h70
  text "PROJECT TITLE:" at 11343.5,277.5 h45
  text ".PRJ_Title" at 11393.5,144.17 h70
  text "DESIGNED FOR:" at 11343.5,-23.5 h45
  text ".PRJ_Customer" at 11393.5,-163.5 h70
  text "D" at -416.5,-231.5 h70
  text "D" at 14383.5,-231.5 h70
  text "FILE NAME:" at 11343.5,-323.5 h45
  text ".PCB_File_Name_No_Path" at 11393.5,-443.5 h70
  text "Texas Instruments (TI) and/or its licensors do not warrant the accuracy or completeness of this specification" at 6374,-605.34 h45
  text "ENGINEER:" at 11343.5,-613.5 h45
  text "LAYOUT BY:" at 12848.5,-613.5 h45
  text "or any information contained therein. TI and/or its licensors do not warrant that this design will meet" at 6329.01,-718 h45
  text ".PRJ_Engineer" at 11393.5,-768.49 h70
  text ".PCB_Layout" at 12899,-768.49 h70
  text "the specifications, will be suitable for your application or fit for any particular purpose, or will operate in" at 6329.01,-830.67 h45
  text ".Layer_Name" at 577,-858.49 h60
  text "ALTIUM DESIGNER VERSION:" at 12848.5,-923.5 h45
  text "an implementation. TI and/or its licensors do not warrant that the design is production worthy. You should" at 6329.01,-943.33 h45
  text "completely validate and test your design implementation to confirm the system functionality for your application." at 6374,-1056 h45
  text ".print_Scale" at 11393.5,-1056.83 h70
  text ".Application_BuildNumber" at 12899,-1056.83 h70
  text "1" at 739.84,-1263.5 h70
  text "2" at 3235.5,-1263.5 h70
  text "3" at 5724.84,-1263.5 h70
  text "4" at 8231.51,-1263.5 h70
  text "5" at 10730.5,-1263.5 h70
  text "6" at 13235.5,-1263.5 h70
M10 Fab Notes:
  drawing of 189 lines, arcs and shapes, not listed
  text "DESIGN INFORMATION" at 12381.52,6356.17 h60
  text "MIN. TRACK WIDTH:" at 11736.96,6224.05 h60
  text "10" at 12833.2,6224.05 h60
  text "MIL" at 12987.96,6224.05 h60
  text "8" at 12844,6101 h60
  text "MIN. CLEARANCE:" at 11736.96,6099.92 h60
  text "MIL" at 12987.96,6099.92 h60
  text "17.7" at 12749,5981 h60
  text "MIN. VIA PAD SIZE:" at 11736.96,5975.8 h60
  text "MIL" at 12987.96,5975.8 h60
  text "0.05mm (2MIL)" at 12431.96,5845.9 h60
  text "MINIMUM ANNULAR RING" at 11407.73,5837.67 h60
  text "EXTERNAL" at 13139.96,5837.67 h60
  text "PER" at 11607.73,5727.55 h60
  text "IPC-D-275 CLASS 2 LEVEL C" at 11827.73,5727.54 h60
  text "MIL, HOLES" at 13315.96,5627.07 h60
  text "+/-" at 12923.5,5618.48 h60
  text "+/-" at 13777.5,5618.48 h60
  text "REGISTRATION TOLERANCES:" at 11407.73,5617.42 h60
  text "METAL" at 12607.5,5617.42 h60
  text "5" at 13183.7,5617.42 h60
  text "3" at 14016.7,5617.42 h60
  text "MIL" at 14132.96,5617.42 h60
  text "HOLE SIZE TOLERANCE (UNLESS OTHERWISE SPECIFIED):" at 11407.73,5519.1 h60
  text "+/-" at 13777.5,5516.23 h60
  text "3" at 14016.7,5515.17 h60
  text "MIL" at 14132.96,5515.17 h60
  text "MATERIAL:" at 11332.96,5377.52 h60
  text "FR-4 High Tg" at 12319.4,5249 h60
  text "X" at 12174.96,5241.01 h60
  text "FR-408" at 11753.96,5236.49 h60
  text "OTHER" at 13241.96,5236.49 h60
  text "40 MIL (1.0mm) +/-10%" at 12074.06,5093.46 h60
  text "X" at 11953.96,5091.01 h60
  text "THICKNESS:" at 11407.73,5085.24 h60
  text "OTHER" at 13358.96,5085.24 h60
  text "TOLERANCE:" at 11407.73,4946.92 h60
  text "X" at 12255.96,4946.92 h60
  text "ANSI IPC-6012 TYPE 3 CLASS 2" at 12433.98,4946.92 h60
  text "OTHER +/-" at 12433.96,4802.73 h60
  text "BOW & TWIST:" at 11407.73,4657.54 h60
  text "X" at 12255.96,4657.54 h60
  text "ANSI IPC-6012 TYPE 3 CLASS 2" at 12433.98,4657.54 h60
  text "OTHER +/-" at 12433.96,4510.85 h60
  text "DRILLING:" at 11332.96,4380.23 h60
  text "NC_DRILL FILES" at 13093.96,4275.04 h60
  text "REFERENCE:" at 11407.73,4271.1 h60
  text "X" at 12064.96,4271.01 h60
  text "AS SHOWN" at 12242.96,4271.1 h60
  text "X" at 12965.96,4271.1 h60
  text "OTHER" at 13391.96,4128.85 h60
  text "PTH COPPER THICKNESS:" at 11407.41,4125.32 h60
  text "X" at 12546.64,4125.32 h60
  text "20-30 um" at 12674.64,4125.32 h60
  text "BOARD FINISH:" at 11332.96,3977.73 h60
  text "SILKSCREEN:" at 11488.18,3867.6 h60
  text "X" at 12445.96,3867.6 h60
  text "TOP" at 12562.96,3867.6 h60
  text "BOTTOM" at 13073.96,3867.6 h60
  text "SILKSCREEN COLOR:" at 11488.18,3712.41 h60
  text "X" at 12444.96,3712.41 h60
  text "WHITE" at 12562.96,3712.41 h60
  text "OTHER" at 13073.96,3712.41 h60
  text "X" at 12575.96,3568.96 h60
  text "GREEN" at 12693.96,3568.96 h60
  text "OTHER" at 13311.96,3568.96 h60
  text "SOLDER RESIST COLOR:" at 11488.18,3562.1 h60
  text "X" at 12575.96,3414.71 h60
  text "MATTE" at 12693.96,3414.71 h60
  text "SEMI-GLOSS" at 13311.5,3414.07 h60
  text "IMMERSION GOLD (ENIG)" at 12393.96,3241.94 h60
  text "ENEPIG" at 13731.5,3234.72 h60
  text "SURFACE FINISH:" at 11332.96,3233.72 h60
  text "X" at 12215.96,3233.72 h60
  text "IMM. TIN/SILVER OR EQUIV" at 11662.5,3096.4 h60
  text "OTHER" at 13093.96,3092.47 h60
  text "ARRAY/PANEL:" at 11332.96,2937.09 h60
  text "CUT AND TRIM PER M1 BOARD OUTLINE" at 12393.96,2928.87 h60
  text "N.C. ROUTE" at 12393.96,2792.9 h60
  text "X" at 13081.96,2792.9 h60
  text "V. SCORE" at 13259.96,2792.9 h60
  text "CERTIFICATION:" at 11332.96,2663.77 h60
  text "MATERIALS AND WORKMANSHIP FOR ALL PCBS" at 12057.96,2663.77 h60
  text "TO MEET OR EXCEED THE REQUIREMENTS OF:" at 12057.96,2569.71 h60
  text "X" at 11695.47,2441.08 h60
  text "ANSI IPC-A-600F CLASS ->" at 11823.46,2441.08 h60
  text "X" at 13471.47,2441.08 h60
  text "2" at 13581.46,2441.08 h60
  text "1" at 13266.46,2439.58 h60
  text "3" at 13935.46,2439.58 h60
  text "X" at 12507.47,2293.39 h60
  text "RoHS" at 12635.46,2293.39 h60
  text "OTHER" at 13279.86,2293.39 h60
  text "PER ORDER" at 13676.92,2293.39 h60
  text "ALL BOARDS MUST MEET OR EXCEED UL94-V0 REQUIREMENTS." at 11360.5,2139.57 h60
  text "PCB MUST BEAR THE UL94V-0 UL REGISTERED MATERIAL ID NUMBER" at 11360.5,2023.5 h60
  text "ADDITIONAL REQUIREMENTS:" at 11332.96,1854.08 h60
  text "MICROSECTION:" at 11407.73,1746.95 h60
  text "YES" at 12313.46,1746.95 h60
  text "REQUIRED" at 13174.96,1602.62 h60
  text "BARE BOARD ELEC. TEST:" at 11407.73,1599.76 h60
  text "NONE" at 12713.46,1599.76 h60
  text "X" at 13056.96,1599.76 h60
  text "PER ORDER" at 13766.96,1599.76 h60
  text "X" at 11462.47,1450.08 h60
  text "5.91 MIL VIAS REQUIRE NON-CONDUCTIVE FILL AND PLANARIZE" at 11545,1393 h56
  text "X" at 11465.47,1294.08 h60
  text "8 MIL VIAS REQUIRE NON-CONDUCTIVE FILL AND PLANARIZE" at 11548,1230 h56
  text "OUTER XX MIL TRACES REQUIRE 50 OHM SINGLE-ENDED IMPEDANCE" at 11582.89,1127.46 h58
  text "LAYER 2 & 3 (INNER LAYERS) XX MIL WIDE, XX MIL SPACE / TRACES REQUIRE 100 OHM DIFFERENTIAL IMPEDANCE" at 11574.89,891.74 h60
  text ".Layer_Name" at 577,-858.49 h60
M11 Gerber Information:
  lines w10: -292,-930.17 6308,-930.17 ; -292,-726.83 6310,-726.83 ; -292,-523.5 -292,-1133.5 3713,-1133.5 6310,-1133.5 6310,-523.5 -291.5,-523.5 -291.5,-1133.5 1284,-1133.5 ; 2173,-1133.5 2173,-523.5 ; 3440,-726.83 3440,-523.5 ; 4280,-726.83 4280,-523.5 ; 4902,-1140 4902,-937.17
  text "ALL ARTWORK VIEWED FROM TOP SIDE" at -228.5,-655.67 h60
  text "BOARD #:" at 2248,-655.67 h60
  text ".PRJ_Number" at 2793.5,-655.67 h60
  text "REV:" at 3638,-655.67 h60
  text ".PCB_Rev" at 3929.5,-655.67 h60
  text "SVN REV:" at 4476,-655.67 h60
  text ".VersionControl_RevNumber" at 4982,-655.67 h60
  text "LAYER NAME =" at -228.5,-858.49 h60
  text "TID #:" at 2248,-859 h60
  text ".TID" at 2793.5,-859 h60
  text "PLOT NAME =" at -228.5,-1064.34 h60
  text ".plot_File_Name" at 577,-1064.34 h60
  text "GENERATED    :" at 2250,-1064.34 h60
  text ".Print_Date" at 3119.5,-1064.34 h60
  text ".Print_Time" at 3848.5,-1064.34 h60
  text "TEXAS INSTRUMENTS" at 5113,-1064.34 h60
M12 Stackup:
  drawing of 269 lines, arcs and shapes, not listed
  text "Layer" at 9796.35,7797.5 h60
  text "Name" at 10206.26,7797.5 h60
  text "Material" at 11146,7797.5 h60
  text "Thickness" at 12005.77,7797.5 h60
  text "Constant" at 12655.6,7797.5 h60
  text "Board Layer Stack" at 13225.46,7797.5 h60
  text "Top Overlay" at 10206.26,7677.5 h60
  text "Top Solder" at 10206.26,7557.5 h60
  text "Solder Resist" at 11146,7557.5 h60
  text "0.40mil" at 12005.77,7557.5 h60
  text "3.5" at 12655.6,7557.5 h60
  text "1" at 9796.35,7437.5 h60
  text "Top Layer" at 10206.26,7437.5 h60
  text "2.76mil" at 12005.77,7437.5 h60
  text "Dielectric 1" at 10206.26,7317.5 h60
  text "FR-4 High Tg" at 11146,7317.5 h60
  text "5.00mil" at 12005.77,7317.5 h60
  text "4.2" at 12655.6,7317.5 h60
  text "2" at 9796.35,7197.5 h60
  text "Signal Layer 1" at 10206.26,7197.5 h60
  text "2.76mil" at 12005.77,7197.5 h60
  text "Dielectric 2" at 10206.26,7077.5 h60
  text "FR-4 High Tg" at 11146,7077.5 h60
  text "19.00mil" at 12005.77,7077.5 h60
  text "4.2" at 12655.6,7077.5 h60
  text "3" at 9796.35,6957.5 h60
  text "Signal Layer 2" at 10206.26,6957.5 h60
  text "2.76mil" at 12005.77,6957.5 h60
  text "Dielectric 3" at 10206.26,6837.5 h60
  text "FR-4 High Tg" at 11146,6837.5 h60
  text "5.00mil" at 12005.77,6837.5 h60
  text "4.2" at 12655.6,6837.5 h60
  text "4" at 9796.35,6717.5 h60
  text "Bottom Layer" at 10206.26,6717.5 h60
  text "2.76mil" at 12005.77,6717.5 h60
  text "Bottom Solder" at 10206.26,6597.5 h60
  text "Solder Resist" at 11146,6597.5 h60
  text "0.40mil" at 12005.77,6597.5 h60
  text "3.5" at 12655.6,6597.5 h60
  text ".Layer_Name" at 577,-858.49 h60
M13 Component Bodies Top:
  text ".Layer_Name" at 577,-858.49 h60
M14 Component Bodies Bottom:
  text ".Layer_Name" at 577,-858.49 h60
M15 Courtyards Top:
  text ".Layer_Name" at 577,-858.49 h60
M16 Courtyards Bottom:
  text ".Layer_Name" at 577,-858.49 h60
Drill Drawing:
  circle w10: c3194.54,2671.69 r27.56
  lines w10: 3166.98,2327.17 3222.1,2327.17 3194.54,2272.05 3166.98,2327.17 ; 3166.98,2396.07 3222.1,2396.07 3222.1,2451.2 3166.98,2451.2 3166.98,2396.07 ; 3166.98,2520.1 3194.54,2533.88 3222.1,2520.1 3208.32,2547.66 3222.1,2575.22 3194.54,2561.44 3166.98,2575.22 3180.76,2547.66 3166.98,2520.1 ; 3166.98,2781.93 3180.76,2781.93 3194.54,2768.15 3208.32,2781.93 3222.1,2781.93 3208.32,2795.71 3222.1,2809.5 3208.32,2809.5 3194.54,2823.28 3180.76,2809.5 3166.98,2809.5 3180.76,2795.71 3166.98,2781.93
  lines w12: 3117,2234.84 6343.8,2234.84 ; 3117,2854.97 6343.8,2854.97 ; 3454.36,2110.81 3454.36,2979 ; 3786.06,2110.81 3786.06,2979 ; 4421.91,2110.81 4421.91,2979 ; 4680.71,2110.81 4680.71,2979 ; 5055.46,2110.81 5055.46,2979 ; 5778,2110.81 5778,2979 ; 3117,2110.81 6343.8,2110.81 6343.8,2979 3117,2979 3117,2110.81
  text "Symbol" at 3191.42,2892.18 h72
  text "Quantity" at 3491.57,2892.18 h72
  text "Finished Hole Size" at 3823.26,2892.18 h72
  text "Plated" at 4459.12,2892.18 h72
  text "Hole Type" at 4717.92,2892.18 h72
  text "Drill Layer Pair" at 5092.67,2892.18 h72
  text "Hole Tolerance" at 5815.21,2892.18 h72
  text "3" at 3491.57,2768.15 h60
  text "5.91mil (0.150mm)" at 3823.26,2768.15 h60
  text "PTH" at 4459.12,2768.15 h60
  text "Round" at 4717.92,2768.15 h60
  text "Top Layer - Bottom Layer" at 5092.67,2768.15 h60
  text "242" at 3491.57,2644.13 h60
  text "8.00mil (0.203mm)" at 3823.26,2644.13 h60
  text "PTH" at 4459.12,2644.13 h60
  text "Round" at 4717.92,2644.13 h60
  text "Top Layer - Bottom Layer" at 5092.67,2644.13 h60
  text "1" at 3491.57,2520.1 h60
  text "40.00mil (1.016mm)" at 3823.26,2520.1 h60
  text "PTH" at 4459.12,2520.1 h60
  text "Round" at 4717.92,2520.1 h60
  text "Top Layer - Bottom Layer" at 5092.67,2520.1 h60
  text "4" at 3491.57,2396.07 h60
  text "43.31mil (1.100mm)" at 3823.26,2396.07 h60
  text "PTH" at 4459.12,2396.07 h60
  text "Round" at 4717.92,2396.07 h60
  text "Top Layer - Bottom Layer" at 5092.67,2396.07 h60
  text "22" at 3491.57,2272.05 h60
  text "45.28mil (1.150mm)" at 3823.26,2272.05 h60
  text "PTH" at 4459.12,2272.05 h60
  text "Round" at 4717.92,2272.05 h60
  text "Top Layer - Bottom Layer" at 5092.67,2272.05 h60
  text "272 Total" at 3491.57,2148.02 h60
Mechanical 17:
  text ".Layer_Name" at 577,-858.49 h60
Mechanical 18:
  text ".Layer_Name" at 577,-858.49 h60
Mechanical 19:
  text ".Layer_Name" at 577,-858.49 h60

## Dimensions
0,-400 to 1000,-400 on M2 Board Dimensions
0,0 to 0,3000 on M2 Board Dimensions
0,0 to 3000,0 on M2 Board Dimensions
